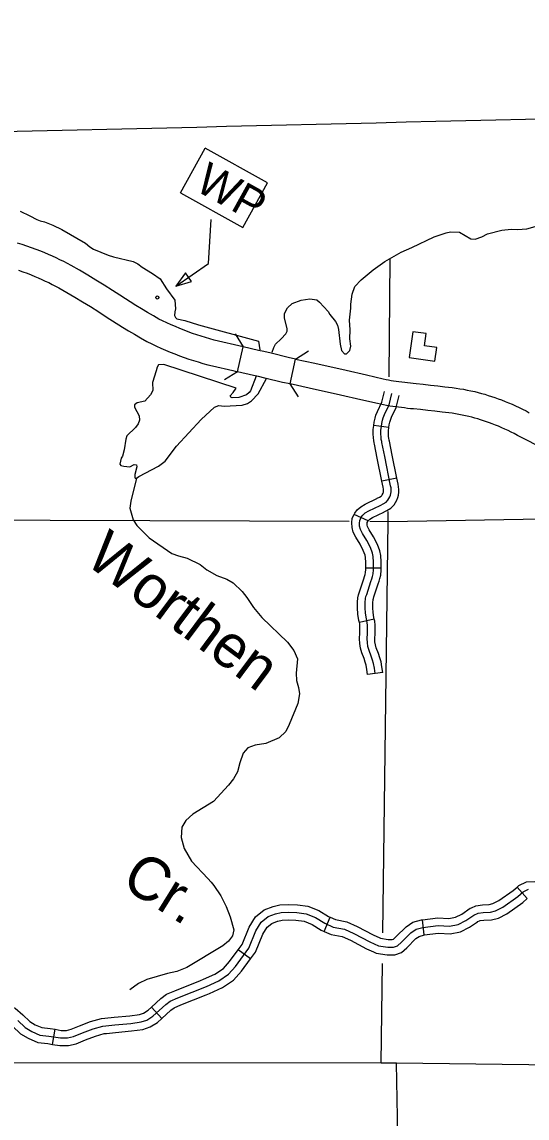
# Model space of a CAD drawing. Extents: x -19 to 366, y -4 to 359.
# Drawn here: x 136.698 to 137.635, y 197.944 to 199.977 of the extents above; entities that cross this region are included whole.
import ezdxf

# ---------------------------------------------------------------- set-up
doc = ezdxf.new("R2010")
doc.units = 0
for name, color, linetype in [('Level 10', 7, 'Continuous'), ('Level 32', 7, 'Continuous'), ('Level 35', 7, 'Continuous'), ('Level 37', 7, 'Continuous'), ('Level 4', 7, 'Continuous'), ('Level 45', 7, 'Continuous'), ('Level 5', 7, 'Continuous'), ('Level 57', 7, 'Continuous'), ('Level 58', 7, 'Continuous'), ('Level 60', 7, 'Continuous'), ('Level 9', 7, 'Continuous')]:
    doc.layers.add(name, color=color, linetype=linetype)

msp = doc.modelspace()

# ---------------------------------------------------------------- linework, layer by layer
at = {"layer": 'Level 10'}
for p, q in [((137.0973, 199.328), (137.1082, 199.374)), ((137.195, 199.3053), (137.2052, 199.3515))]:
    msp.add_line(p, q, dxfattribs=at)
for points in [[(137.1082, 199.374), (137.0996, 199.3761), (137.0623, 199.3847), (137.0543, 199.3868), (137.0462, 199.3891), (137.0381, 199.3914), (137.0301, 199.3939), (137.0221, 199.3965), (137.0141, 199.3992), (137.0062, 199.4021), (136.9985, 199.405), (136.9906, 199.4082), (136.9825, 199.4116), (136.9745, 199.4151), (136.9665, 199.4187), (136.9586, 199.4223), (136.9515, 199.4257), (136.9415, 199.4316), (136.9306, 199.4381), (136.9196, 199.4446), (136.909, 199.4509), (136.8794, 199.4698), (136.8657, 199.4788), (136.8499, 199.4888), (136.8349, 199.4981), (136.8198, 199.5072), (136.8045, 199.5161), (136.789, 199.525), (136.782, 199.5287), (136.7751, 199.5322), (136.7681, 199.5357), (136.7611, 199.5391), (136.754, 199.5423), (136.7469, 199.5455), (136.7398, 199.5486), (136.7324, 199.5516), (136.7238, 199.5549), (136.7153, 199.5579), (136.7067, 199.5609), (136.6982, 199.5638), (136.6896, 199.5665)], [(136.6914, 199.5161), (136.6994, 199.5133), (136.7073, 199.5105), (136.715, 199.5076), (136.7214, 199.5049), (136.728, 199.5021), (136.7345, 199.4992), (136.7409, 199.4962), (136.7473, 199.4932), (136.7537, 199.49), (136.76, 199.4867), (136.7662, 199.4835), (136.7809, 199.4751), (136.7956, 199.4665), (136.8102, 199.4577), (136.8248, 199.4487), (136.84, 199.439), (136.8537, 199.4301), (136.8842, 199.4105), (136.8955, 199.4038), (136.9064, 199.3974), (136.9174, 199.3909), (136.9292, 199.3839), (136.9385, 199.3795), (136.9469, 199.3756), (136.9554, 199.3718), (136.9639, 199.3681), (136.9724, 199.3645), (136.9812, 199.3609), (136.9899, 199.3576), (136.9985, 199.3545), (137.0071, 199.3516), (137.0158, 199.3488), (137.0245, 199.3461), (137.0333, 199.3435), (137.0421, 199.3411), (137.051, 199.3388), (137.0888, 199.33), (137.0973, 199.328)], [(137.2052, 199.3515), (137.1917, 199.3545), (137.1597, 199.3622), (137.1464, 199.3655), (137.1366, 199.3673), (137.1082, 199.374)], [(137.2052, 199.3515), (137.2406, 199.3438), (137.2988, 199.3307), (137.3365, 199.3221), (137.3678, 199.3151), (137.3729, 199.3138), (137.3776, 199.3128), (137.3823, 199.3119), (137.387, 199.3111), (137.3918, 199.3104), (137.3969, 199.3098), (137.4023, 199.3091), (137.4076, 199.3084), (137.4128, 199.3078), (137.4181, 199.3072), (137.4233, 199.3066), (137.4286, 199.3061), (137.442, 199.3048), (137.4554, 199.3033), (137.4688, 199.3019), (137.4821, 199.3003), (137.4889, 199.2996), (137.4958, 199.2987), (137.5028, 199.2977), (137.5097, 199.2966), (137.5167, 199.2954), (137.5235, 199.2941), (137.5304, 199.2926), (137.5374, 199.2911), (137.5437, 199.2895), (137.55, 199.2878), (137.5562, 199.2861), (137.5624, 199.2842), (137.5686, 199.2822), (137.5747, 199.2802), (137.5809, 199.278), (137.5869, 199.2757), (137.5936, 199.2731), (137.6002, 199.2704), (137.6068, 199.2676), (137.6133, 199.2646), (137.6198, 199.2616), (137.6262, 199.2584), (137.6326, 199.2552), (137.6386, 199.252)], [(137.195, 199.3053), (137.1811, 199.3083), (137.1484, 199.3162), (137.1364, 199.3192), (137.1268, 199.321), (137.0973, 199.328)], [(137.6694, 199.183), (137.6167, 199.21), (137.6107, 199.2132), (137.605, 199.2161), (137.5993, 199.2189), (137.5935, 199.2216), (137.5877, 199.2242), (137.5818, 199.2268), (137.5759, 199.2292), (137.57, 199.2315), (137.5646, 199.2335), (137.5593, 199.2354), (137.5539, 199.2372), (137.5484, 199.239), (137.5429, 199.2406), (137.5375, 199.2422), (137.532, 199.2436), (137.5265, 199.245), (137.5204, 199.2464), (137.5142, 199.2476), (137.5081, 199.2488), (137.5019, 199.2499), (137.4957, 199.2509), (137.4895, 199.2518), (137.4833, 199.2526), (137.4768, 199.2533), (137.4635, 199.2548), (137.4503, 199.2563), (137.4371, 199.2577), (137.4239, 199.259), (137.4184, 199.2595), (137.4129, 199.2601), (137.4073, 199.2608), (137.4018, 199.2614), (137.3962, 199.2621), (137.3909, 199.2628), (137.3855, 199.2635), (137.3797, 199.2643), (137.3739, 199.2653), (137.3681, 199.2664), (137.3624, 199.2677), (137.3571, 199.2689), (137.326, 199.2759), (137.2883, 199.2845), (137.2304, 199.2976), (137.195, 199.3053)]]:
    msp.add_lwpolyline(points, dxfattribs=at)
at = {"layer": 'Level 32'}
for p, q in [((137.3784, 199.2248), (137.3501, 199.228)), ((137.393, 199.1308), (137.3652, 199.1252)), ((137.3395, 199.0514), (137.3138, 199.0635)), ((137.364, 198.9639), (137.3356, 198.9637)), ((137.3512, 198.8694), (137.3235, 198.8632)), ((137.3668, 198.7704), (137.3387, 198.7666))]:
    msp.add_line(p, q, dxfattribs=at)
for points in [[(137.3501, 199.228), (137.3502, 199.2283), (137.351, 199.2346), (137.3526, 199.2417), (137.3542, 199.2472), (137.3569, 199.2545), (137.365, 199.2715), (137.37, 199.2911)], [(137.37, 199.249), (137.3785, 199.2666), (137.3838, 199.2877)], [(137.3784, 199.2248), (137.379, 199.2297), (137.3801, 199.2346), (137.3812, 199.2383), (137.3831, 199.2435), (137.3919, 199.2618), (137.3975, 199.2842)], [(137.3643, 199.2265), (137.365, 199.2322), (137.3664, 199.2382), (137.3677, 199.2427), (137.37, 199.249)], [(137.3652, 199.1252), (137.3565, 199.1678), (137.3513, 199.1938), (137.3509, 199.196), (137.3501, 199.2003), (137.3494, 199.2055), (137.349, 199.2127), (137.3493, 199.2207), (137.3501, 199.228)], [(137.3649, 199.1987), (137.3641, 199.2025), (137.3636, 199.2068), (137.3633, 199.2128), (137.3635, 199.2197), (137.3643, 199.2265)], [(137.393, 199.1308), (137.3844, 199.1734), (137.3792, 199.1993), (137.3788, 199.2014), (137.3782, 199.2048), (137.3777, 199.208), (137.3775, 199.213), (137.3777, 199.2186), (137.3784, 199.2248)], [(137.3704, 199.1706), (137.3653, 199.1966), (137.3649, 199.1987)], [(137.373, 199.0862), (137.3764, 199.0899), (137.378, 199.0927), (137.38, 199.0961), (137.3812, 199.0991), (137.382, 199.102), (137.3825, 199.1055), (137.3825, 199.1092), (137.3822, 199.1124), (137.3814, 199.1164), (137.3704, 199.1706)], [(137.3137, 199.0635), (137.3148, 199.0657), (137.3196, 199.0717), (137.3259, 199.0776), (137.3343, 199.0825), (137.3559, 199.0929), (137.3566, 199.0933), (137.3607, 199.0953), (137.3638, 199.0973), (137.3649, 199.0984), (137.3657, 199.0998), (137.3673, 199.1025), (137.3677, 199.1036), (137.368, 199.1048), (137.3683, 199.1064), (137.3683, 199.1086), (137.3681, 199.1104), (137.3675, 199.1137), (137.3652, 199.1252)], [(137.3395, 199.0514), (137.3405, 199.0523), (137.3431, 199.0547), (137.3477, 199.0574), (137.3687, 199.0675), (137.3696, 199.068), (137.3746, 199.0705), (137.3821, 199.0752), (137.3878, 199.0814), (137.3903, 199.0855), (137.3927, 199.0898), (137.3947, 199.0945), (137.396, 199.0993), (137.3967, 199.1045), (137.3967, 199.1098), (137.3963, 199.1143), (137.3954, 199.1192), (137.393, 199.1308)], [(137.345, 198.9392), (137.3466, 198.944), (137.3479, 198.9483), (137.3491, 198.9532), (137.3499, 198.9609), (137.3498, 198.9749), (137.3491, 198.9852), (137.3478, 198.9916), (137.3438, 199.0019), (137.3374, 199.0149), (137.3293, 199.0282), (137.3255, 199.0357), (137.324, 199.0413), (137.3236, 199.0471), (137.3243, 199.0524), (137.3269, 199.0581), (137.3301, 199.062), (137.3345, 199.0662), (137.341, 199.07), (137.3623, 199.0802), (137.3631, 199.0806)], [(137.3631, 199.0806), (137.3677, 199.0829), (137.373, 199.0862)], [(137.3356, 198.9637), (137.3356, 198.9744), (137.3349, 198.9834), (137.3341, 198.9877), (137.3308, 198.9962), (137.3249, 199.0081), (137.3168, 199.0213), (137.3122, 199.0306), (137.3099, 199.0389), (137.3094, 199.0476), (137.3104, 199.0564), (137.3138, 199.0635)], [(137.364, 198.9639), (137.364, 198.9755), (137.3632, 198.9871), (137.3615, 198.9956), (137.3568, 199.0076), (137.3498, 199.0218), (137.3417, 199.0351), (137.3388, 199.0408), (137.3381, 199.0436), (137.3379, 199.0467), (137.3381, 199.0485), (137.3395, 199.0514)], [(137.3235, 198.8632), (137.3227, 198.8669), (137.3206, 198.8784), (137.3201, 198.89), (137.3202, 198.9008), (137.3208, 198.9089), (137.3218, 198.9144), (137.3235, 198.9196), (137.3316, 198.9438), (137.3331, 198.9482), (137.3342, 198.952), (137.3351, 198.9556), (137.3356, 198.9615), (137.3356, 198.9637)], [(137.3512, 198.8694), (137.3505, 198.8725), (137.3489, 198.8816), (137.3485, 198.8904), (137.3486, 198.8995), (137.3491, 198.9054), (137.3494, 198.9073), (137.3505, 198.9105), (137.3585, 198.9347), (137.3602, 198.9397), (137.3616, 198.9445), (137.3632, 198.9507), (137.3641, 198.9603), (137.364, 198.9639)], [(137.3349, 198.9072), (137.3356, 198.9109), (137.337, 198.9151), (137.345, 198.9392)], [(137.3527, 198.7685), (137.3514, 198.7783), (137.3498, 198.7871), (137.3481, 198.7934), (137.3456, 198.8008), (137.3414, 198.8113), (137.3394, 198.8183), (137.3383, 198.8257), (137.3379, 198.8327), (137.3383, 198.8432), (137.3388, 198.8507), (137.3388, 198.8572), (137.3381, 198.863), (137.3366, 198.8697), (137.3348, 198.88), (137.3343, 198.8902), (137.3344, 198.9002), (137.3349, 198.9072)], [(137.3387, 198.7666), (137.3374, 198.776), (137.3359, 198.784), (137.3345, 198.7893), (137.3323, 198.7959), (137.328, 198.8067), (137.3255, 198.8152), (137.3241, 198.8243), (137.3237, 198.8326), (137.3241, 198.8439), (137.3246, 198.8512), (137.3246, 198.8564), (137.3241, 198.8607), (137.3235, 198.8632)], [(137.3668, 198.7704), (137.3654, 198.7806), (137.3636, 198.7902), (137.3617, 198.7975), (137.3589, 198.8057), (137.3549, 198.8158), (137.3533, 198.8213), (137.3524, 198.8272), (137.3522, 198.8329), (137.3525, 198.8425), (137.353, 198.8502), (137.353, 198.858), (137.3521, 198.8654), (137.3512, 198.8694)]]:
    msp.add_lwpolyline(points, dxfattribs=at)
at = {"layer": 'Level 35'}
for points in [[(136.91, 199.1305), (136.8995, 199.0881), (136.898, 199.0748), (136.9038, 199.0532), (136.9106, 199.0427), (136.9338, 199.02), (136.9755, 198.9909), (136.988, 198.9864), (137.0043, 198.9823), (137.0282, 198.9703), (137.0407, 198.9604), (137.0593, 198.9499), (137.0778, 198.9431), (137.0896, 198.9367), (137.1063, 198.9205), (137.115, 198.9091), (137.1268, 198.8906), (137.1424, 198.8724), (137.1902, 198.8267), (137.202, 198.8108), (137.2089, 198.7957), (137.2063, 198.7687), (137.2068, 198.7555), (137.2106, 198.7426), (137.2122, 198.7308), (137.2096, 198.7126), (137.1935, 198.6738), (137.1871, 198.6605), (137.1747, 198.6491), (137.1498, 198.6384), (137.1305, 198.6357), (137.1169, 198.6307), (137.1079, 198.6208), (137.1019, 198.6029), (137.0975, 198.5858), (137.0903, 198.5733), (137.0809, 198.5611), (137.0527, 198.5307), (137.0146, 198.5074), (137.0018, 198.4959), (136.9939, 198.4834), (136.9932, 198.4644), (136.9982, 198.444), (137.0123, 198.4205), (137.0427, 198.388), (137.0485, 198.3812)], [(137.0485, 198.3812), (137.0537, 198.3752), (137.0663, 198.3559), (137.0766, 198.3362), (137.0839, 198.3173), (137.0904, 198.2927), (137.0882, 198.282), (137.081, 198.2717), (137.0701, 198.2634), (137.0033, 198.2229), (136.9852, 198.2156), (136.9675, 198.2118), (136.9293, 198.2006), (136.9139, 198.1937), (136.898, 198.1819)]]:
    msp.add_lwpolyline(points, dxfattribs=at)
at = {"layer": 'Level 37'}
for points in [[(137.0933, 199.3982), (137.1082, 199.374)], [(137.2052, 199.3515), (137.2291, 199.3669)], [(137.0973, 199.328), (137.0731, 199.313)], [(137.2104, 199.2814), (137.195, 199.3053)]]:
    msp.add_lwpolyline(points, dxfattribs=at)
at = {"layer": 'Level 4'}
msp.add_lwpolyline([(139.2314, 198.0374), (138.3894, 198.0333), (138.3734, 198.0335), (137.3923, 198.046), (137.3636, 198.046), (136.3894, 198.0464), (136.3709, 198.0464), (135.3908, 198.0464), (135.3637, 198.047), (134.4615, 198.0663), (134.4184, 198.067), (133.4674, 198.0826)], dxfattribs=at)
at = {"layer": 'Level 45'}
for p, q in [((137.6345, 198.3509), (137.616, 198.3724)), ((137.258, 198.2902), (137.2694, 198.3162)), ((137.4439, 198.2836), (137.4407, 198.3118)), ((137.1216, 198.239), (137.0987, 198.2559)), ((136.9569, 198.1286), (136.9378, 198.1496)), ((136.7545, 198.0805), (136.7592, 198.1085))]:
    msp.add_line(p, q, dxfattribs=at)
for points in [[(137.4286, 198.294), (137.4413, 198.2975), (137.4697, 198.3008), (137.4906, 198.2998), (137.5066, 198.3028), (137.5207, 198.31), (137.5357, 198.3204), (137.5435, 198.3237), (137.553, 198.3253), (137.5664, 198.3256), (137.5762, 198.3283), (137.5895, 198.3351), (137.6176, 198.355), (137.6271, 198.3632), (137.6369, 198.3681)], [(137.5313, 198.334), (137.5395, 198.3374), (137.5516, 198.3395), (137.5643, 198.3398), (137.571, 198.3416), (137.5822, 198.3473), (137.6089, 198.3662), (137.616, 198.3724)], [(137.616, 198.3724), (137.6192, 198.3751), (137.6333, 198.3822), (137.6484, 198.3827), (137.665, 198.3796), (137.6875, 198.3718), (137.7054, 198.3605), (137.7137, 198.3562), (137.7213, 198.354)], [(137.5422, 198.3077), (137.5475, 198.31), (137.5544, 198.3111), (137.5684, 198.3115), (137.5813, 198.3149), (137.5969, 198.3229), (137.6264, 198.3438), (137.6345, 198.3509)], [(137.0987, 198.2559), (137.1059, 198.2656), (137.1188, 198.2978), (137.1308, 198.3169), (137.1468, 198.3299), (137.1636, 198.3364), (137.1659, 198.3368)], [(137.1659, 198.3368), (137.1761, 198.3391), (137.1915, 198.3402), (137.2086, 198.3391), (137.2281, 198.3366), (137.2485, 198.3286), (137.2661, 198.3177), (137.2694, 198.3162)], [(137.4407, 198.3118), (137.4692, 198.3151), (137.4897, 198.3141), (137.502, 198.3164), (137.5133, 198.3222), (137.5288, 198.3329), (137.5313, 198.334)], [(136.6897, 198.1251), (136.7038, 198.1117), (136.7158, 198.1045), (136.7305, 198.0979), (136.7478, 198.096), (136.7694, 198.0924), (136.7821, 198.0924), (136.7935, 198.095), (136.8099, 198.1019), (136.8295, 198.1094), (136.8477, 198.1146), (136.8699, 198.1169), (136.8993, 198.1195), (136.9186, 198.1221), (136.9294, 198.1257), (136.9401, 198.1326), (136.9646, 198.1548), (136.9728, 198.161), (136.9868, 198.1669), (137.04, 198.1881), (137.0626, 198.1982), (137.0809, 198.2106), (137.0936, 198.225), (137.1184, 198.2587), (137.1315, 198.2913), (137.1416, 198.3073), (137.154, 198.3175), (137.1677, 198.3227), (137.1782, 198.325), (137.1915, 198.326), (137.2072, 198.325), (137.2245, 198.3227), (137.2422, 198.3158), (137.2595, 198.3051), (137.2751, 198.2982), (137.2957, 198.2943), (137.3133, 198.2864), (137.3427, 198.2708), (137.3587, 198.2636), (137.376, 198.261), (137.3868, 198.261), (137.394, 198.2632), (137.4015, 198.2701), (137.4191, 198.2877), (137.4286, 198.294)], [(137.1216, 198.239), (137.1309, 198.2517), (137.1442, 198.2849), (137.1524, 198.2978), (137.1612, 198.305), (137.1718, 198.3091), (137.172, 198.3091)], [(137.172, 198.3091), (137.1802, 198.3109), (137.1916, 198.3117), (137.2058, 198.3108), (137.221, 198.3088), (137.2358, 198.3031), (137.2528, 198.2925), (137.258, 198.2902)], [(137.2694, 198.3162), (137.2794, 198.3119), (137.3, 198.3079), (137.3196, 198.2992), (137.349, 198.2835), (137.3613, 198.278)], [(137.3613, 198.278), (137.3628, 198.2773), (137.3771, 198.2752), (137.3846, 198.2752), (137.3867, 198.2758), (137.3917, 198.2804), (137.4101, 198.2988), (137.4226, 198.307), (137.4386, 198.3115), (137.4407, 198.3118)], [(137.4439, 198.2836), (137.4702, 198.2866), (137.4916, 198.2856), (137.5112, 198.2892), (137.528, 198.2978), (137.5425, 198.3079), (137.5422, 198.3077)], [(137.258, 198.2902), (137.2709, 198.2845), (137.2914, 198.2806), (137.3071, 198.2737), (137.3365, 198.258), (137.3497, 198.2521)], [(137.3497, 198.2521), (137.3547, 198.2498), (137.375, 198.2468), (137.389, 198.2468), (137.4013, 198.2507), (137.4113, 198.2598), (137.4281, 198.2767), (137.4345, 198.2809), (137.4441, 198.2836), (137.4439, 198.2836)], [(137.0291, 198.199), (137.0345, 198.2012), (137.0556, 198.2107), (137.0714, 198.2214), (137.0825, 198.234), (137.0987, 198.2559)], [(137.0396, 198.1726), (137.0456, 198.175), (137.0695, 198.1858), (137.0903, 198.1999), (137.1046, 198.2161), (137.1216, 198.239)], [(136.9378, 198.1496), (136.9555, 198.1657), (136.9656, 198.1734), (136.9815, 198.18), (137.0291, 198.199)], [(136.9569, 198.1286), (136.9737, 198.1439), (136.9799, 198.1486), (136.9922, 198.1537), (137.0396, 198.1726)], [(136.6758, 198.1516), (136.6848, 198.1477), (136.6992, 198.1356), (136.7124, 198.1231), (136.7224, 198.1171), (136.7343, 198.1118), (136.7498, 198.1101), (136.7592, 198.1085)], [(136.8514, 198.1293), (136.8686, 198.131), (136.8977, 198.1336), (136.9154, 198.136), (136.9232, 198.1386), (136.9315, 198.1439), (136.9378, 198.1496)], [(136.6647, 198.1255), (136.6698, 198.1233), (136.6802, 198.1145), (136.6951, 198.1003), (136.7093, 198.0918), (136.7268, 198.0841), (136.7459, 198.0819), (136.7545, 198.0805)], [(136.7592, 198.1085), (136.7706, 198.1066), (136.7805, 198.1066), (136.7892, 198.1086), (136.8046, 198.115), (136.825, 198.1229), (136.845, 198.1286), (136.8514, 198.1293)], [(136.8543, 198.101), (136.8713, 198.1028), (136.9009, 198.1054), (136.9218, 198.1082), (136.9355, 198.1128), (136.9488, 198.1212), (136.9569, 198.1286)], [(136.7545, 198.0805), (136.7682, 198.0782), (136.7837, 198.0782), (136.7979, 198.0814), (136.8152, 198.0887), (136.834, 198.0959), (136.8504, 198.1006), (136.8543, 198.101)]]:
    msp.add_lwpolyline(points, dxfattribs=at)
at = {"layer": 'Level 5'}
for points in [[(137.379, 199.3184), (137.3808, 199.5382)], [(137.3768, 199.0505), (137.377, 199.0685)], [(137.3768, 199.0505), (137.9853, 199.061)], [(136.3794, 199.0537), (137.3045, 199.0507)], [(137.343, 199.0506), (137.3768, 199.0505)], [(137.3668, 198.2874), (137.3768, 199.0505)], [(137.3636, 198.046), (137.3661, 198.2307)], [(137.406, 197.3116), (137.3923, 198.046)]]:
    msp.add_lwpolyline(points, dxfattribs=at)
at = {"layer": 'Level 57'}
for p, q in [((136.9915, 199.6598), (137.0373, 199.7426)), ((137.1533, 199.6784), (137.0373, 199.7426)), ((137.1074, 199.5956), (137.1533, 199.6784)), ((136.9915, 199.6598), (137.1074, 199.5956))]:
    msp.add_line(p, q, dxfattribs=at)
msp.add_lwpolyline([(136.983, 199.4868), (137.0435, 199.5289), (137.0488, 199.6105)], dxfattribs=at)
msp.add_lwpolyline([(137.0123, 199.4954), (137.0012, 199.5112), (136.983, 199.4868)], close=True, dxfattribs=at)
msp.add_circle((136.9487, 199.4657), 0.00284, dxfattribs=at)
at = {"layer": 'Level 58'}
msp.add_lwpolyline([(137.4157, 199.3546), (137.4634, 199.3478), (137.4669, 199.373), (137.4444, 199.3761), (137.4475, 199.3987), (137.4224, 199.4022)], close=True, dxfattribs=at)
at = {"layer": 'Level 60'}
for points in [[(139.4406, 1.5315), (139.2511, 10.1473), (139.0608, 18.7633), (138.8699, 27.3793), (138.6784, 35.9956), (138.4861, 44.6119), (138.2932, 53.2285), (138.0997, 61.8451), (137.9055, 70.4619), (137.7106, 79.0789), (137.5151, 87.6959), (137.319, 96.3132), (137.1221, 104.9306), (136.9247, 113.5481), (136.7265, 122.1658), (136.5278, 130.7836), (136.3283, 139.4016), (136.1282, 148.0197), (135.9275, 156.6379), (135.7261, 165.2564), (135.5241, 173.8749), (135.3214, 182.4936), (135.1181, 191.1125), (134.9141, 199.7315), (134.7095, 208.3506), (134.5043, 216.9699), (134.2984, 225.5894), (134.0919, 234.209), (133.8847, 242.8288), (133.6769, 251.4487), (133.4685, 260.0687), (133.2594, 268.6889), (133.0497, 277.3093), (132.8393, 285.9298), (132.6283, 294.5504), (132.4167, 303.1713), (132.2044, 311.7922), (131.9916, 320.4133), (131.778, 329.0346), (131.5639, 337.656), (131.3491, 346.2776)], [(0, 198.1326), (7.1014, 198.137), (14.2028, 198.1503), (21.3042, 198.1724), (28.4055, 198.2034), (35.5068, 198.2433), (42.6081, 198.292), (49.7092, 198.3496), (56.8103, 198.4161), (63.9113, 198.4913), (71.0123, 198.5755), (78.1131, 198.6685), (85.2137, 198.7704), (92.3143, 198.8811), (99.4147, 199.0007), (106.5149, 199.1291), (113.615, 199.2664), (120.7149, 199.4126), (127.8146, 199.5676), (134.9141, 199.7315), (142.0135, 199.9042), (149.1125, 200.0858), (156.2114, 200.2762), (163.31, 200.4755), (170.4084, 200.6837), (177.5065, 200.9007), (184.6043, 201.1265), (191.7018, 201.3612), (198.799, 201.6048), (205.896, 201.8572), (212.9926, 202.1185), (220.0888, 202.3886), (227.1848, 202.6676), (234.2803, 202.9554), (241.3755, 203.2521), (248.4704, 203.5576), (255.5648, 203.872), (262.6589, 204.1952), (269.7525, 204.5273), (276.8457, 204.8682), (283.9385, 205.218), (291.0309, 205.5766), (298.1228, 205.9441), (305.2142, 206.3204), (312.3051, 206.7056), (319.3956, 207.0996), (326.4856, 207.5024), (333.5751, 207.9141), (340.664, 208.3347)], [(0, 189.5162), (7.1121, 189.5206), (14.2243, 189.5339), (21.3364, 189.556), (28.4484, 189.5869), (35.5605, 189.6267), (42.6725, 189.6754), (49.7844, 189.7329), (56.8962, 189.7992), (64.0079, 189.8744), (71.1196, 189.9584), (78.2311, 190.0512), (85.3425, 190.1529), (92.4538, 190.2635), (99.5649, 190.3829), (106.6759, 190.5111), (113.7867, 190.6482), (120.8974, 190.7941), (128.0078, 190.9489), (135.1181, 191.1125), (142.2282, 191.2849), (149.338, 191.4662), (156.4476, 191.6563), (163.5569, 191.8553), (170.666, 192.0631), (177.7749, 192.2798), (184.8835, 192.5053), (191.9917, 192.7396), (199.0997, 192.9828), (206.2074, 193.2348), (213.3147, 193.4956), (220.4218, 193.7653), (227.5285, 194.0438), (234.6348, 194.3312), (241.7408, 194.6274), (248.8464, 194.9324), (255.9516, 195.2463), (263.0564, 195.569), (270.1608, 195.9005), (277.2648, 196.2409), (284.3683, 196.5901), (291.4715, 196.9481), (298.5741, 197.315), (305.6763, 197.6907), (312.7781, 198.0753), (319.8793, 198.4686), (326.9801, 198.8708), (334.0804, 199.2818), (341.1801, 199.7017)]]:
    msp.add_spline(points, degree=3, dxfattribs=at)
at = {"layer": 'Level 9'}
for points in [[(136.6942, 199.6257), (136.712, 199.6174), (136.7252, 199.6102), (136.7317, 199.6076), (136.7396, 199.6057), (136.7552, 199.6001), (136.7714, 199.5915), (136.8158, 199.5666), (136.8238, 199.5598), (136.8302, 199.5556), (136.8575, 199.5444), (136.8677, 199.541), (136.9037, 199.5324), (136.9124, 199.5279), (136.9203, 199.5218), (136.9397, 199.5102), (136.9537, 199.5003), (136.9655, 199.4818), (136.9811, 199.4606), (136.9824, 199.4446)], [(137.3075, 199.4456), (137.3074, 199.4531), (137.3104, 199.4721), (137.3152, 199.4862), (137.3269, 199.4987), (137.3488, 199.517), (137.3706, 199.5323), (137.4008, 199.5498), (137.4208, 199.5583), (137.4619, 199.5782), (137.4842, 199.5858), (137.4925, 199.5874), (137.5092, 199.5867), (137.5304, 199.5746), (137.5383, 199.5739), (137.5504, 199.5781), (137.5614, 199.5835), (137.5874, 199.5908), (137.6048, 199.5924), (137.6169, 199.592), (137.6343, 199.5928), (137.6581, 199.5998)], [(137.1616, 199.3642), (137.165, 199.3732), (137.1678, 199.3793), (137.1786, 199.389), (137.1872, 199.3986), (137.1894, 199.4032), (137.1898, 199.4078), (137.1844, 199.4282), (137.1844, 199.4362), (137.19, 199.4468), (137.1991, 199.4548), (137.2157, 199.4606), (137.2315, 199.4629), (137.2444, 199.4615), (137.2493, 199.4573), (137.2653, 199.4399), (137.2687, 199.4342), (137.279, 199.4214), (137.2832, 199.4142)], [(137.2832, 199.4142), (137.2847, 199.4062), (137.2879, 199.3793), (137.2906, 199.3675), (137.2959, 199.3615), (137.2993, 199.3611), (137.3057, 199.3672), (137.3075, 199.3756), (137.306, 199.3892), (137.3067, 199.4055), (137.3054, 199.4237), (137.3075, 199.4456)], [(136.9824, 199.4446), (136.981, 199.4392), (136.9806, 199.4324), (136.9825, 199.4286), (136.9848, 199.4263), (136.9995, 199.4233), (137.0253, 199.4151), (137.1362, 199.3844), (137.1391, 199.3687)], [(136.9512, 199.3409), (136.9482, 199.3367), (136.9468, 199.3295), (136.9397, 199.3082), (136.9401, 199.2934), (136.936, 199.2851), (136.9258, 199.2737), (136.9111, 199.2706), (136.9066, 199.2664), (136.9066, 199.2622), (136.9153, 199.2463), (136.9154, 199.2383), (136.9131, 199.2311), (136.9083, 199.2247), (136.8921, 199.2094), (136.8902, 199.203), (136.8873, 199.1832), (136.8839, 199.1714), (136.8816, 199.1676), (136.879, 199.1563), (136.8813, 199.1544), (136.8866, 199.1529), (136.898, 199.1518), (136.9059, 199.156), (136.9101, 199.1556), (136.9108, 199.1518), (136.9071, 199.1374), (136.9068, 199.1321), (136.9079, 199.1309), (136.9102, 199.1306), (136.9147, 199.134), (136.9509, 199.1531), (136.9633, 199.1619), (136.9844, 199.19), (137.0299, 199.2392), (137.0548, 199.262), (137.0627, 199.2655), (137.0726, 199.264), (137.1062, 199.266), (137.116, 199.2691), (137.1236, 199.274), (137.136, 199.287), (137.1515, 199.3155)], [(137.1323, 199.3197), (137.1216, 199.2926), (137.1193, 199.2892), (137.1144, 199.2854), (137.0997, 199.2804), (137.0876, 199.2796), (137.085, 199.2807), (137.0838, 199.2834), (137.0895, 199.2895), (137.0947, 199.2978), (136.9611, 199.3417), (136.9512, 199.3409)]]:
    msp.add_lwpolyline(points, dxfattribs=at)

# ---------------------------------------------------------------- texts
at = {"layer": 'Level 35'}
for s, rotation, p in [('Worthen', 323.2968, (136.8117, 198.9742)), ('Cr.', 328.1651, (136.8785, 198.375))]:
    msp.add_text(s, height=0.08, rotation=rotation, dxfattribs=at).set_placement(p)
at = {"layer": 'Level 57'}
msp.add_text('WP', height=0.06, rotation=331.0332, dxfattribs=at).set_placement((137.0158, 199.6661))

doc.saveas('drawing.dxf')
